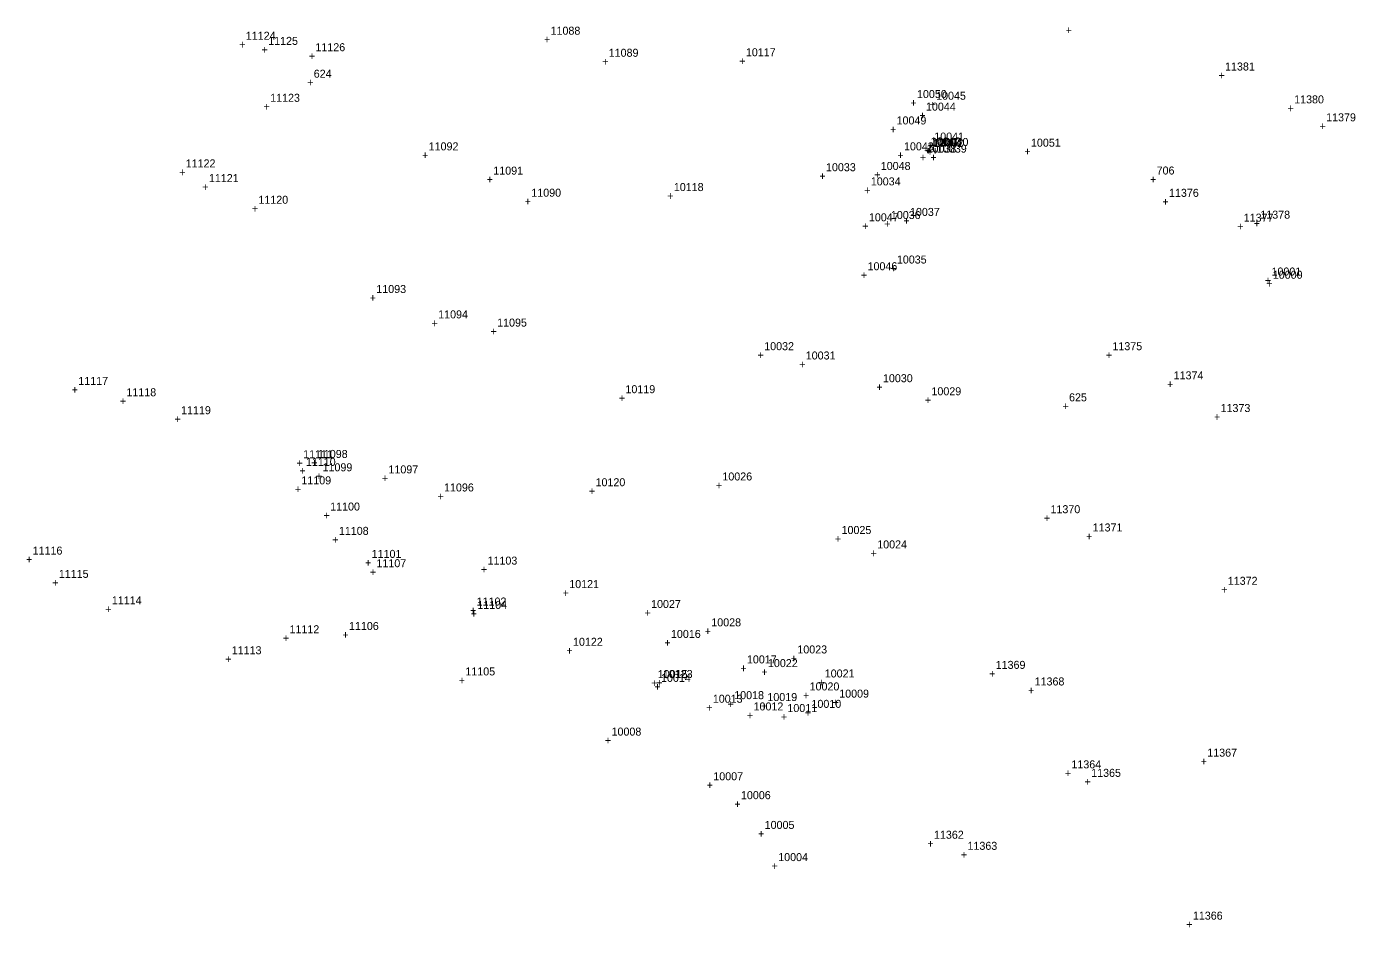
# Model space of a CAD drawing. Extents: x 1160051 to 1162814, y 614604 to 619560.
# Drawn here: x 1160051.2 to 1160466.3, y 614946.8 to 615228.1 of the extents above; entities that cross this region are included whole.
import ezdxf

# ---------------------------------------------------------------- set-up
doc = ezdxf.new("R2010")
doc.units = 0
for name, color, linetype in [('S_Control_Temp_Traverse', 7, 'Continuous'), ('S_Control_Traverse_Point', 7, 'Continuous'), ('S_Drainage_Culvert_Top', 7, 'Continuous'), ('S_Drainage_Invert', 7, 'Continuous'), ('S_Ground_Elevation', 7, 'Continuous'), ('S_Roadway_Drive_Paved', 7, 'Continuous'), ('S_Traffic_Sign_DoublePost', 7, 'Continuous'), ('S_Traffic_Sign_SinglePost', 7, 'Continuous'), ('S_Trees_TreeLine', 7, 'Continuous'), ('S_Utilities_UG_Electrical_MH', 7, 'Continuous')]:
    doc.layers.add(name, color=color, linetype=linetype)

msp = doc.modelspace()

# ---------------------------------------------------------------- texts
at = {"layer": 'S_Control_Temp_Traverse'}
for s, p in [('624', (1160140.92, 615212.16)), ('+', (1160138.86, 615209.41)), ('625', (1160376.87, 615111.1)), ('+', (1160374.81, 615108.35))]:
    msp.add_text(s, height=2.5, dxfattribs=at).set_placement(p)
at = {"layer": 'S_Control_Traverse_Point'}
for s, p in [('706', (1160404.23, 615181.93)), ('706', (1160404.23, 615181.93)), ('706', (1160404.23, 615181.93)), ('706', (1160404.23, 615181.93)), ('706', (1160404.23, 615181.93)), ('+', (1160402.17, 615179.18)), ('+', (1160402.17, 615179.18)), ('+', (1160402.17, 615179.18)), ('+', (1160402.17, 615179.18)), ('+', (1160402.17, 615179.18))]:
    msp.add_text(s, height=2.5, dxfattribs=at).set_placement(p)
at = {"layer": 'S_Drainage_Culvert_Top'}
for s, p in [('10002', (1160334.51, 615190.54)), ('+', (1160332.45, 615187.79)), ('10001', (1160440.12, 615150.39)), ('+', (1160438.06, 615147.64))]:
    msp.add_text(s, height=2.5, dxfattribs=at).set_placement(p)
at = {"layer": 'S_Drainage_Invert'}
for s, p in [('10003', (1160334.03, 615190.88)), ('+', (1160331.97, 615188.13)), ('10000', (1160440.52, 615149.38)), ('+', (1160438.46, 615146.63))]:
    msp.add_text(s, height=2.5, dxfattribs=at).set_placement(p)
at = {"layer": 'S_Ground_Elevation'}
for s, p in [('11124', (1160119.7, 615224.02)), ('11088', (1160214.91, 615225.59)), ('+', (1160375.81, 615225.76)), ('+', (1160117.64, 615221.27)), ('+', (1160124.64, 615219.66)), ('11125', (1160126.7, 615222.41)), ('11126', (1160141.45, 615220.43)), ('+', (1160212.85, 615222.84)), ('11089', (1160233.07, 615218.7)), ('10117', (1160275.92, 615218.86)), ('+', (1160139.39, 615217.68)), ('+', (1160231.01, 615215.95)), ('+', (1160273.86, 615216.11)), ('+', (1160423.55, 615211.66)), ('11381', (1160425.61, 615214.41)), ('+', (1160327.32, 615203.06)), ('10050', (1160329.38, 615205.81)), ('+', (1160333.29, 615202.53)), ('10045', (1160335.35, 615205.28)), ('11380', (1160447.2, 615204.14)), ('+', (1160330.11, 615199.13)), ('10044', (1160332.18, 615201.88)), ('+', (1160445.14, 615201.39)), ('11379', (1160457.19, 615198.54)), ('+', (1160320.94, 615194.82)), ('10049', (1160323, 615197.57)), ('+', (1160455.13, 615195.79)), ('10042', (1160333.68, 615191.01)), ('10041', (1160334.77, 615192.53)), ('10040', (1160336.14, 615190.84)), ('10051', (1160364.98, 615190.62)), ('+', (1160174.77, 615186.72)), ('11092', (1160176.83, 615189.47)), ('+', (1160323.26, 615186.73)), ('10043', (1160325.32, 615189.48)), ('+', (1160330.3, 615186)), ('+', (1160331.62, 615188.26)), ('10038', (1160332.36, 615188.75)), ('+', (1160332.71, 615189.78)), ('+', (1160333.55, 615186.01)), ('+', (1160334.08, 615188.09)), ('10039', (1160335.61, 615188.76)), ('+', (1160362.92, 615187.87)), ('11122', (1160100.93, 615184.15)), ('11091', (1160197.02, 615181.89)), ('10033', (1160300.95, 615182.96)), ('10048', (1160318.06, 615183.35)), ('+', (1160098.87, 615181.4)), ('11121', (1160108.17, 615179.56)), ('+', (1160194.96, 615179.14)), ('+', (1160298.89, 615180.21)), ('+', (1160316, 615180.6)), ('+', (1160106.11, 615176.81)), ('11090', (1160208.9, 615175)), ('+', (1160251.35, 615174.01)), ('10118', (1160253.41, 615176.76)), ('11376', (1160408.1, 615174.96)), ('+', (1160121.58, 615170.05)), ('11120', (1160123.64, 615172.8)), ('+', (1160206.84, 615172.25)), ('10037', (1160327.19, 615169)), ('+', (1160406.04, 615172.21)), ('10047', (1160314.35, 615167.32)), ('+', (1160319.15, 615165.28)), ('10036', (1160321.21, 615168.03)), ('+', (1160325.13, 615166.25)), ('11377', (1160431.44, 615167.21)), ('+', (1160434.57, 615165.4)), ('11378', (1160436.63, 615168.15)), ('+', (1160312.29, 615164.57)), ('+', (1160429.38, 615164.46)), ('10035', (1160323.09, 615154.13)), ('+', (1160311.87, 615149.29)), ('10046', (1160313.93, 615152.04)), ('+', (1160321.03, 615151.38)), ('11093', (1160160.48, 615144.92)), ('+', (1160158.42, 615142.17)), ('11094', (1160179.8, 615137)), ('+', (1160177.74, 615134.25)), ('11095', (1160198.22, 615134.44)), ('+', (1160196.16, 615131.69)), ('+', (1160279.59, 615124.32)), ('10032', (1160281.65, 615127.07)), ('+', (1160388.36, 615124.32)), ('11375', (1160390.42, 615127.07)), ('11117', (1160067.39, 615116.22)), ('10030', (1160318.74, 615117.07)), ('11374', (1160409.55, 615117.96)), ('+', (1160065.33, 615113.47)), ('11118', (1160082.41, 615112.68)), ('10119', (1160238.3, 615113.64)), ('+', (1160316.68, 615114.32)), ('10029', (1160333.89, 615112.99)), ('+', (1160407.49, 615115.21)), ('+', (1160080.35, 615109.93)), ('11119', (1160099.49, 615107.08)), ('+', (1160236.24, 615110.89)), ('+', (1160331.83, 615110.24)), ('11373', (1160424.21, 615107.75)), ('+', (1160097.43, 615104.33)), ('+', (1160422.15, 615105)), ('+', (1160140.16, 615090.67)), ('11098', (1160142.22, 615093.42)), ('11097', (1160164.27, 615088.6)), ('10026', (1160268.58, 615086.39)), ('+', (1160162.2, 615085.85)), ('11096', (1160181.63, 615082.95)), ('10120', (1160228.96, 615084.58)), ('+', (1160266.52, 615083.64)), ('+', (1160179.57, 615080.2)), ('+', (1160226.9, 615081.83)), ('+', (1160144, 615074.24)), ('11100', (1160146.06, 615076.99)), ('11370', (1160371.08, 615076.16)), ('10025', (1160305.81, 615069.66)), ('+', (1160369.02, 615073.41)), ('11371', (1160384.25, 615070.46)), ('+', (1160303.75, 615066.91)), ('10024', (1160316.95, 615065.17)), ('+', (1160382.19, 615067.71)), ('11116', (1160053.12, 615063.23)), ('11101', (1160159.02, 615062.21)), ('+', (1160314.89, 615062.42)), ('+', (1160051.06, 615060.48)), ('+', (1160156.96, 615059.46)), ('+', (1160193.16, 615057.36)), ('11103', (1160195.22, 615060.11)), ('+', (1160059.24, 615053.22)), ('11115', (1160061.3, 615055.97)), ('10121', (1160220.74, 615052.78)), ('11372', (1160426.46, 615053.8)), ('+', (1160218.68, 615050.03)), ('+', (1160424.4, 615051.05)), ('+', (1160075.8, 615044.95)), ('11114', (1160077.86, 615047.7)), ('11102', (1160191.82, 615047.33)), ('+', (1160189.76, 615044.58)), ('10016', (1160252.52, 615037.21)), ('10122', (1160221.92, 615034.76)), ('+', (1160250.46, 615034.46)), ('10023', (1160292, 615032.37)), ('+', (1160219.85, 615032.01)), ('10017', (1160276.25, 615029.26)), ('10022', (1160282.82, 615028.1)), ('+', (1160289.94, 615029.62)), ('10015', (1160248.38, 615024.66)), ('10123', (1160249.98, 615024.71)), ('+', (1160274.19, 615026.51)), ('+', (1160280.76, 615025.35)), ('10021', (1160300.56, 615024.87)), ('+', (1160351.9, 615024.8)), ('11369', (1160353.96, 615027.55)), ('+', (1160246.32, 615021.91)), ('+', (1160247.92, 615021.96)), ('10020', (1160295.83, 615020.82)), ('+', (1160298.5, 615022.12)), ('11368', (1160366.12, 615022.37)), ('10018', (1160272.28, 615018.09)), ('10019', (1160282.64, 615017.5)), ('+', (1160293.76, 615018.07)), ('+', (1160364.05, 615019.62)), ('+', (1160270.22, 615015.34)), ('+', (1160280.58, 615014.75)), ('11367', (1160420.06, 615000.14)), ('+', (1160418, 614997.39)), ('11362', (1160334.68, 614974.5)), ('+', (1160332.62, 614971.75)), ('11363', (1160345.15, 614971.04)), ('+', (1160343.09, 614968.29)), ('11366', (1160415.56, 614949.24)), ('+', (1160413.5, 614946.49))]:
    msp.add_text(s, height=2.5, dxfattribs=at).set_placement(p)
at = {"layer": 'S_Roadway_Drive_Paved'}
for s, p in [('+', (1160135.57, 615090.58)), ('11111', (1160137.63, 615093.33)), ('11110', (1160138.48, 615090.95)), ('+', (1160136.42, 615088.2)), ('+', (1160135.01, 615082.42)), ('11109', (1160137.07, 615085.17)), ('11108', (1160148.78, 615069.4)), ('+', (1160146.72, 615066.65)), ('11107', (1160160.52, 615059.29)), ('+', (1160158.45, 615056.54)), ('11104', (1160192.04, 615046.27)), ('+', (1160189.97, 615043.52)), ('11112', (1160133.36, 615038.67)), ('+', (1160149.88, 615036.94)), ('11106', (1160151.94, 615039.69)), ('11113', (1160115.31, 615032.11)), ('+', (1160131.3, 615035.92)), ('+', (1160113.24, 615029.36)), ('11105', (1160188.29, 615025.5)), ('10014', (1160249.41, 615023.49)), ('+', (1160186.23, 615022.75)), ('+', (1160247.35, 615020.74)), ('10013', (1160265.59, 615016.97)), ('10010', (1160296.41, 615015.38)), ('+', (1160303.02, 615015.82)), ('10009', (1160305.08, 615018.57)), ('+', (1160263.53, 615014.22)), ('+', (1160276.26, 615011.82)), ('10012', (1160278.32, 615014.57)), ('10011', (1160288.89, 615014.07)), ('+', (1160294.35, 615012.63)), ('+', (1160286.83, 615011.32)), ('+', (1160231.9, 615003.96)), ('10008', (1160233.96, 615006.71)), ('10007', (1160265.75, 614992.76)), ('+', (1160263.69, 614990.01)), ('10006', (1160274.38, 614986.86)), ('+', (1160272.32, 614984.11)), ('+', (1160279.73, 614974.82)), ('10005', (1160281.79, 614977.57)), ('10004', (1160286.02, 614967.52)), ('+', (1160283.96, 614964.77))]:
    msp.add_text(s, height=2.5, dxfattribs=at).set_placement(p)
at = {"layer": 'S_Traffic_Sign_DoublePost'}
for s, p in [('11364', (1160377.61, 614996.48)), ('+', (1160375.55, 614993.73)), ('+', (1160381.73, 614991.08)), ('11365', (1160383.79, 614993.83))]:
    msp.add_text(s, height=2.5, dxfattribs=at).set_placement(p)
at = {"layer": 'S_Traffic_Sign_SinglePost'}
for s, p in [('11123', (1160127.32, 615204.64)), ('+', (1160125.26, 615201.89))]:
    msp.add_text(s, height=2.5, dxfattribs=at).set_placement(p)
at = {"layer": 'S_Trees_TreeLine'}
for s, p in [('10034', (1160314.95, 615178.53)), ('+', (1160312.89, 615175.78)), ('10031', (1160294.62, 615124.17)), ('+', (1160292.56, 615121.42)), ('10027', (1160246.31, 615046.56)), ('+', (1160244.25, 615043.81)), ('10028', (1160265.12, 615040.83)), ('+', (1160263.06, 615038.08))]:
    msp.add_text(s, height=2.5, dxfattribs=at).set_placement(p)
at = {"layer": 'S_Utilities_UG_Electrical_MH'}
for s, p in [('+', (1160141.62, 615086.5)), ('11099', (1160143.68, 615089.25))]:
    msp.add_text(s, height=2.5, dxfattribs=at).set_placement(p)

doc.saveas('drawing.dxf')
